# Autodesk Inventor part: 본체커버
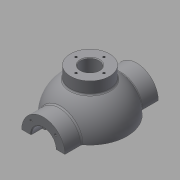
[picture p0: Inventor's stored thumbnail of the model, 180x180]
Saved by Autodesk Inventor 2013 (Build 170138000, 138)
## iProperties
Created: 2015-12
Part Number: 본체커버
Material: 알루미늄 6061
Document SubType Name: Modeling
Designer: mduedu
Density: 2.71 g/cm^3
Mass: 547.265 g
Surface Area: 428.16 cm^2
Volume: 201.943 cm^3
Author: mduedu
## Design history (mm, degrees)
sketch "스케치1"
  geometry: L1 (-53, 0)-(53, 0); A1 r 53 centre (0, 0) between (53, 0) and (-53, 0); 2 further points
  constraints: 2 coincident, 2 end point, 2 point on circle, 1 centre point, 1 horizontal, 1 midpoint
  dimensions: "d0" = 53 radius of A1
revolve "회전1" sketch "스케치1" stored, may be unused: angle "d2" = 90 deg
feature "쉘1" dims "d11" = 10
node "작업 평면1"
sketch "스케치2"
  geometry: C1 r 31 at (0, 0); 1 further point
  constraints: 1 centre point, 1 coincident
  dimensions: "d4" = 62 diameter of C1
extrude "돌출1" join sketch "스케치2" stored distance "d5" = 10; taper "d6" = 0 deg
hole "구멍1" diameter "d14" = 35; stored, may be unused: countersink angle "d18" = 90 deg, drill point angle "d20" = 0 deg; dims "d12" = 10, "d13" = 10, "d15" = 6, "d16" = 4, "d17" = 2, "d19" = 16
hole "구멍2" diameter "d23" = 27; stored, may be unused: countersink angle "d27" = 90 deg, drill point angle "d29" = 0 deg; dims "d21" = 10, "d22" = 10, "d24" = 6, "d25" = 4, "d26" = 2, "d28" = 16
fillet "모깎기1" dims "d30" = 0.3
chamfer "모따기1" distance "d40" = 1; stored, may be unused: second distance "d41" = 2, angle "d42" = 45 deg
sketch "스케치4"
  geometry: L1 (0, 0)-(0, -25); L2 (0, 0)-(-17.678, -17.678); A1 r 25 centre (0, 0) between (-17.678, -17.678) and (0, -25); 1 further point
  constraints: 4 end point, 2 point on circle, 1 centre point, 1 coincident, 1 vertical
  dimensions: "d43" = 50 diameter of A1; "d47" = 45 deg angle of L1 L2
hole "구멍4" sketch "스케치4" at (-17.678, -17.678) diameter "d49" = 3.242; stored, may be unused: countersink angle "d53" = 90 deg, drill point angle "d55" = 118 deg; dims "d50" = 11, "d51" = 4, "d52" = 2, "d54" = 13
node "작업 평면3"
sketch "스케치6"
  geometry: C1 r 65 at (0, 0); 1 further point
  constraints: 1 centre point, 1 coincident
  dimensions: "d78" = 130 diameter of C1
extrude "돌출3" join sketch "스케치6" distance "d80" = 10; taper "d81" = 0 deg
sketch "스케치7"
  geometry: C1 r 20 at (0, 0); 1 further point
  constraints: 1 centre point, 1 coincident
  dimensions: "d82" = 40 diameter of C1
extrude "돌출4" join sketch "스케치7" stored distance "d84" = 10; taper "d85" = 0 deg
sketch "스케치8"
  geometry: 2 further points
  constraints: 1 coincident
hole "구멍6" sketch "스케치8" at (0, 0) diameter "d86" = 20; stored, may be unused: countersink angle "d90" = 90 deg, drill point angle "d92" = 118 deg; dims "d87" = 7, "d88" = 40, "d89" = 5, "d91" = 10
fillet "모깎기2" dims "d93" = 0.3
sketch "스케치9"
  geometry: L1 (65, -75)-(-65, -75) reference; L2 (-45, -75)-(-38.245, -36.692); A1 r 53 centre (0, 0) between (42.988, 31) and (42.988, -31) reference; 1 further point
  constraints: 2 end point, 1 point on circle, 1 point on line
  dimensions: "d94" = 45 horizontal distance of L2.start point (0, 0); "d95" = 80 deg angle of L2 L1
feature "리브1" sketch "스케치9" dims "d96" = 1, "d97" = 8, "d98" = 0, "d99" = 0, "d100" = 1, "d101" = 1
sketch "스케치10"
  geometry: L1 (0, 0)-(0, -55); L2 (0, 0)-(-38.891, -38.891); A1 r 55 centre (0, 0) between (0, -55) and (-38.891, -38.891); 2 further points
  constraints: 4 end point, 2 coincident, 2 point on circle, 1 centre point, 1 vertical
  dimensions: "d105" = 110 diameter of A1; "d107" = 45 deg angle of L1 L2
hole "구멍7" sketch "스케치10" at (-38.891, -38.891) diameter "d109" = 10; stored, may be unused: countersink angle "d113" = 90 deg, drill point angle "d115" = 118 deg; dims "d110" = 7, "d111" = 40, "d112" = 5, "d114" = 10
fillet "모깎기3" dims "d120" = 3
fillet "모깎기4" dims "d121" = 3, "d122" = 3
fillet "모깎기5" dims "d123" = 3
fillet "모깎기6" dims "d124" = 3
sketch "스케치11"
  geometry: C1 r 5 at (-38.891, 38.891) reference; C2 r 5 at (38.891, 38.891) reference; C3 r 5 at (38.891, -38.891) reference; C4 r 5 at (-38.891, -38.891) reference; C5 r 20 at (0, 0) reference; C6 r 65 at (0, 0) reference; 1 further point
  constraints: 3 other
feature "엠보싱1" sketch "스케치11" dims "d125" = 0.5, "d126" = 0
sketch "스케치12"
  geometry: L1 (0, 100)-(0, -100); L2 (0, 100)-(-150, 100); L3 (-150, 100)-(-150, -100); L4 (-150, -100)-(0, -100); 2 further points
  constraints: 8 end point, 3 perpendicular, 1 coincident, 1 midpoint, 1 vertical
  dimensions: "d127" = 200 distance of L2.end L3.end; "d129" = 150 distance of L3.end L1.end
extrude "돌출5" cut sketch "스케치12" stored distance "d130" = 10; taper "d131" = 0 deg
node "작업 평면4"
sketch "스케치16"
  geometry: C1 r 28 at (0, 0); 1 further point
  constraints: 1 centre point, 1 coincident
  dimensions: "d148" = 56 diameter of C1
extrude "돌출9" join sketch "스케치16" stored distance "d150" = 5; taper "d151" = 0 deg
hole "구멍8" diameter "d154" = 26; stored, may be unused: countersink angle "d158" = 90 deg, drill point angle "d160" = 118 deg; dims "d152" = 10, "d153" = 10, "d155" = 6, "d156" = 4, "d157" = 2, "d159" = 8
sketch "스케치17" dims "d161" = 40
  geometry: 3 further points
  constraints: 2 vertical alignment, 1 coincident, 2 other
hole "구멍9" sketch "스케치17" at (0, 20) diameter "d163" = 3.242; stored, may be unused: countersink angle "d167" = 90 deg, drill point angle "d169" = 118 deg; dims "d164" = 8, "d165" = 4, "d166" = 2, "d168" = 10
fillet "모깎기11" dims "d173" = 3
chamfer "모따기2" distance "d174" = 1; stored, may be unused: second distance "d175" = 2, angle "d176" = 45 deg
node "솔리드1"
mirror "대칭1"
mirror "대칭2"
pattern_circular "원형 패턴1" dims angle "d57" = 360 deg
mirror "대칭3"
pattern_circular "원형 패턴3" dims angle "d103" = 360 deg
pattern_circular "원형 패턴4" dims "d40" = 1, angle "d118" = 360 deg
pattern_circular "원형 패턴5" dims angle "d171" = 360 deg
node "투영된 루프1"
other parameters: "d3" = 67, "d77" = -85, "d147" = 62
